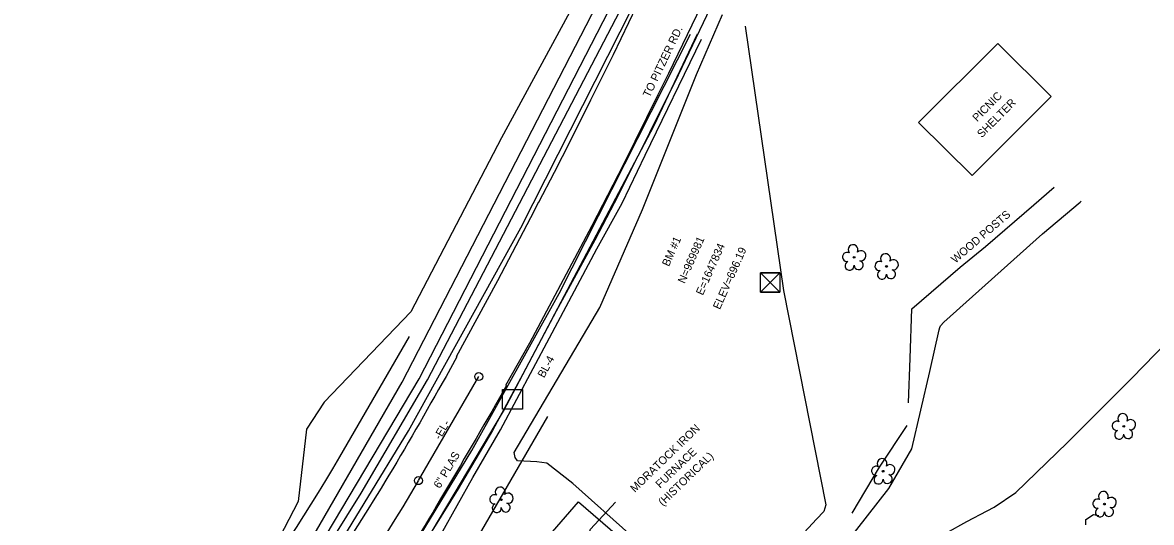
# Model space of a CAD drawing. Extents: x 1645945 to 2447332, y 713118 to 970361.
# Drawn here: x 1647554 to 1647977.1, y 969891.3 to 970078.7 of the extents above; entities that cross this region are included whole.
import ezdxf

# ---------------------------------------------------------------- set-up
doc = ezdxf.new("R2010")
doc.units = 0
for name, color, linetype in [('CTL Secondary Horizontal and Vertical CELL', 7, 'Continuous'), ('CTL Secondary Horizontal and Vertical Text', 7, 'Continuous'), ('CTL Vertical Benchmark CELL', 7, 'Continuous'), ('CTL Vertical Benchmark Text', 7, 'Continuous'), ('Exist Building', 7, 'Continuous'), ('Exist Building Text', 7, 'Continuous'), ('Exist Guardrail', 7, 'Continuous'), ('Exist Horizontal Alignment', 7, 'Continuous'), ('Exist Horizontal Alignment Direction Label', 7, 'Continuous'), ('Exist Horizontal Alignment Station Label', 7, 'Continuous'), ('Exist Hydro Jurisdictional Stream or Body of Water', 7, 'Continuous'), ('Exist Other Culture Fence Line', 7, 'Continuous'), ('Exist Other Culture Fence Line Leader', 7, 'Continuous'), ('Exist Other Culture Fence Line Text', 7, 'Continuous'), ('Exist Right of Way Line', 7, 'Continuous'), ('Exist Roads EOP', 7, 'Continuous'), ('Exist Roads EOP Text', 7, 'Continuous'), ('Exist Roads Soil', 7, 'Continuous'), ('Exist Utilities Sanitary Sewer Forced Main SUE LOS C', 7, 'Continuous'), ('Exist Utilities Sanitary Sewer Forced Main SUE LOS C Text', 7, 'Continuous'), ('Exist Utilities Telephone UG Cable SUE LOS C', 7, 'Continuous'), ('Exist Utilities Telephone UG Conduit SUE LOS B', 7, 'Continuous'), ('Exist Utilities Telephone UG FO SUE LOS C', 7, 'Continuous'), ('Exist Vegetation Tree CELL', 7, 'Continuous'), ('Exist Vegetation Woods Line', 7, 'Continuous')]:
    doc.layers.add(name, color=color, linetype=linetype)

msp = doc.modelspace()

# ---------------------------------------------------------------- linework, layer by layer
at = {"layer": 'CTL Secondary Horizontal and Vertical CELL'}
msp.add_line((1647737.61, 969937.44), (1647737.61, 969937.44), dxfattribs=at)
msp.add_lwpolyline([(1647733.94, 969941.14), (1647741.35, 969941.14), (1647741.35, 969933.71), (1647733.94, 969933.71)], close=True, dxfattribs=at)
at = {"layer": 'CTL Vertical Benchmark CELL'}
msp.add_line((1647834.21, 969981.25), (1647834.21, 969981.25), dxfattribs=at)
msp.add_line((1647834.21, 969981.25), (1647834.21, 969981.25), dxfattribs=at)
msp.add_lwpolyline([(1647830.61, 969984.84), (1647837.8, 969984.84), (1647837.8, 969977.65), (1647830.61, 969977.65)], close=True, dxfattribs=at)
msp.add_lwpolyline([(1647830.61, 969984.84), (1647837.8, 969984.84), (1647837.8, 969977.65), (1647830.61, 969977.65)], close=True, dxfattribs=at)
for points in [[(1647837.8, 969984.84), (1647830.61, 969977.65), (1647834.21, 969981.25), (1647837.8, 969977.65), (1647830.61, 969984.84)], [(1647834.21, 969981.25), (1647837.8, 969984.84), (1647830.61, 969984.84), (1647834.21, 969981.25)], [(1647837.8, 969984.84), (1647830.61, 969977.65), (1647834.21, 969981.25), (1647837.8, 969977.65), (1647830.61, 969984.84)], [(1647834.21, 969981.25), (1647837.8, 969984.84), (1647830.61, 969984.84), (1647834.21, 969981.25)], [(1647834.21, 969981.25), (1647830.61, 969977.65), (1647837.8, 969977.65), (1647834.21, 969981.25)], [(1647834.21, 969981.25), (1647830.61, 969977.65), (1647837.8, 969977.65), (1647834.21, 969981.25)]]:
    msp.add_lwpolyline(points, dxfattribs=at)
at = {"layer": 'Exist Building'}
msp.add_lwpolyline([(1647889.82, 970041.18), (1647909.9, 970021.39), (1647939.56, 970050.99), (1647919.51, 970070.87)], close=True, dxfattribs=at)
at = {"layer": 'Exist Guardrail'}
for points in [[(1647811.77, 970084.13), (1647799.78, 970058.98), (1647789, 970037.41), (1647777.22, 970013.91), (1647768.44, 969997.09), (1647760.77, 969982.88)], [(1647760.77, 969982.88), (1647754.03, 969970.46), (1647741.47, 969946.85), (1647730.08, 969925.76), (1647717.26, 969903.89), (1647707.96, 969889.08), (1647696.73, 969871.06), (1647684.96, 969853.08), (1647670.81, 969832.67), (1647653.24, 969808.63), (1647638.37, 969789.54), (1647629.29, 969778.66)]]:
    msp.add_lwpolyline(points, dxfattribs=at)
at = {"layer": 'Exist Horizontal Alignment'}
msp.add_line((1647702.37, 969906.97), (1647724.96, 969945.99), dxfattribs=at)
msp.add_arc((1647126.83, 970240.1), 665, 298.87121, 329.93673, dxfattribs=at)
at = {"layer": 'Exist Horizontal Alignment Station Label'}
for centre in [(1647724.96, 969945.99), (1647702.37, 969906.97)]:
    msp.add_circle(centre, 1.5, dxfattribs=at)
at = {"layer": 'Exist Hydro Jurisdictional Stream or Body of Water'}
msp.add_lwpolyline([(1647952.53, 969890.44), (1647952.46, 969892.39), (1647955.36, 969894.22), (1647957.42, 969893.91)], dxfattribs=at)
at = {"layer": 'Exist Other Culture Fence Line'}
for points in [[(1647887.25, 969971.32), (1647905.4, 969986.95), (1647914.92, 969994.73), (1647933.07, 970010.39), (1647940.6, 970017)], [(1647886.05, 969936.09), (1647886.68, 969952.9), (1647887.25, 969971.32)], [(1647864.88, 969894.79), (1647875.23, 969912.03), (1647885.58, 969927.64)]]:
    msp.add_lwpolyline(points, dxfattribs=at)
msp.add_lwpolyline([(1647788.87, 969876.21), (1647762.15, 969845.28), (1647735.67, 969868.17), (1647762.41, 969899.05)], close=True, dxfattribs=at)
at = {"layer": 'Exist Other Culture Fence Line Leader'}
msp.add_lwpolyline([(1647761.01, 969872.67), (1647766.89, 969888.75), (1647776.2, 969898.94)], dxfattribs=at)
at = {"layer": 'Exist Right of Way Line'}
for p, q in [((1647672.88, 969915.9), (1647698.99, 969961.02)), ((1647724.81, 969885.85), (1647750.92, 969930.96))]:
    msp.add_line(p, q, dxfattribs=at)
msp.add_arc((1647136.28, 970226.5), 620, 299.46236, 329.93673, dxfattribs=at)
at = {"layer": 'Exist Roads EOP'}
for p, q in [((1647716.78, 969953.44), (1647712.71, 969946.05)), ((1647735.42, 969942.61), (1647731.3, 969935.45))]:
    msp.add_line(p, q, dxfattribs=at)
for points in [[(1647747.48, 970011.4), (1647753.32, 970022.66), (1647759.35, 970034.39), (1647767.01, 970049.78), (1647775.46, 970066.77), (1647784.09, 970084.66), (1647789.56, 970095.71)], [(1647758.89, 969986.43), (1647767.54, 970002.65), (1647779.38, 970025.55), (1647792.2, 970051.77), (1647796.26, 970059.68), (1647806.67, 970081.44), (1647808.71, 970085.73)], [(1647716.61, 969953.53), (1647732.1, 969981.97), (1647744.49, 970005.6), (1647747.5, 970011.45)], [(1647735.19, 969942.75), (1647744.08, 969958.63), (1647758.89, 969986.43)]]:
    msp.add_lwpolyline(points, dxfattribs=at)
for points in [[(1647712.71, 969946.05), (1647689.83, 969906.56), (1647665.85, 969869.13), (1647637.34, 969829.12), (1647607.92, 969794.57), (1647574.53, 969760.72), (1647538.69, 969730.5), (1647499.85, 969702.79), (1647457.34, 969676.33), (1647411.66, 969651.37), (1647366.8, 969630.41), (1647321.37, 969611.83), (1647279.28, 969597.97), (1647224.82, 969583.15), (1647179.92, 969574.15), (1647132.17, 969565.53), (1647083.22, 969557.97), (1647036.22, 969550.58), (1646989.26, 969543.73)], [(1647731.3, 969935.45), (1647707.71, 969895.07), (1647684.27, 969857.13), (1647654.38, 969814.5), (1647624.46, 969779.25), (1647589.97, 969744.66), (1647553.5, 969714.01), (1647512.43, 969684.95), (1647469.3, 969658.19), (1647421.26, 969632.07), (1647375.68, 969609.9), (1647329.15, 969590.49), (1647286.02, 969576.26), (1647230.19, 969561.18), (1647183.04, 969552.75), (1647135.89, 969544.58), (1647086.4, 969536.99), (1647040.14, 969529.53), (1646992.05, 969522.32)]]:
    msp.add_spline(points, degree=3, dxfattribs=at)
at = {"layer": 'Exist Roads Soil'}
for points in [[(1647825.16, 969840.29), (1647854.68, 969873.27), (1647878.69, 969904.08), (1647887.29, 969918.9), (1647894, 969947.84), (1647897.55, 969963.48), (1647897.73, 969964.36), (1647898, 969965.01), (1647899.35, 969966.38), (1647936.25, 969999.54), (1647950.33, 970011.39), (1647950.78, 970011.69)], [(1647833.9, 969820.27), (1647843.63, 969831.63), (1647859.7, 969851.23), (1647864.42, 969856.65), (1647872.24, 969865.05), (1647876.68, 969870.11), (1647881, 969874.71), (1647884.73, 969878.03), (1647892.67, 969883.14), (1647907.86, 969891.64), (1647915.49, 969895.7), (1647918.11, 969897.01), (1647926.28, 969902.5), (1647945.52, 969921.1), (1647969.9, 969945.49), (1647987.24, 969963.4), (1648002.75, 969980.2), (1648005.41, 969983.22)]]:
    msp.add_lwpolyline(points, dxfattribs=at)
at = {"layer": 'Exist Utilities Sanitary Sewer Forced Main SUE LOS C'}
msp.add_lwpolyline([(1647621.71, 969772.62), (1647654.05, 969809.43), (1647680.79, 969846.9), (1647702.42, 969879.41), (1647734.22, 969933.03), (1647790.69, 970040.12), (1647806.93, 970074.53)], dxfattribs=at)
at = {"layer": 'Exist Utilities Telephone UG Cable SUE LOS C'}
for points in [[(1647301.18, 969607.49), (1647346.35, 969625.33), (1647402.72, 969651.12), (1647431.08, 969666.24), (1647439.41, 969670.62), (1647442.16, 969672.78), (1647445.5, 969676.48), (1647448.63, 969678.56), (1647474.06, 969693.41), (1647520.52, 969726.92), (1647556, 969754.87), (1647590.11, 969785.42), (1647617.35, 969813.54), (1647647.46, 969852.3), (1647702.67, 969945.18), (1647775.84, 970087.47)], [(1647299.74, 969604.87), (1647344.43, 969621.93), (1647402.05, 969647.91), (1647428.7, 969661.61), (1647441.47, 969668.79), (1647444.57, 969671.27), (1647446.47, 969673.44), (1647447.93, 969674.84), (1647451.1, 969676.98), (1647475.41, 969691.19), (1647501.84, 969708.82), (1647529.96, 969729.71), (1647548.6, 969744.41), (1647576.21, 969768.81), (1647599.16, 969791.2), (1647624.94, 969819.94), (1647649.96, 969852.56), (1647680.88, 969902.23), (1647705.82, 969944.72), (1647779.36, 970085.84)], [(1647294.11, 969544.68), (1647330.92, 969585.92), (1647342.26, 969590.26), (1647406.15, 969619.43), (1647450.3, 969642.78), (1647488.96, 969665.16), (1647521.25, 969685.99), (1647545.76, 969703.5), (1647563.98, 969716.93), (1647573.87, 969725.16), (1647593.32, 969742.95), (1647627.6, 969780.32), (1647655.82, 969815.07), (1647672.99, 969839.14), (1647691.44, 969867.28), (1647722.34, 969918.27), (1647755.1, 969977.16), (1647804.4, 970074.3)]]:
    msp.add_lwpolyline(points, dxfattribs=at)
at = {"layer": 'Exist Utilities Telephone UG Conduit SUE LOS B'}
msp.add_lwpolyline([(1647528.7, 969688.64), (1647565.5, 969715.45), (1647584.81, 969732.68), (1647602.51, 969750.52), (1647610.22, 969758.56), (1647624.57, 969770.24), (1647632, 969778.64), (1647655.51, 969806.51), (1647671.15, 969829.51), (1647684.31, 969848.46), (1647700.06, 969870.14), (1647710.99, 969887.15), (1647722.81, 969908.11), (1647733.12, 969926.03), (1647751.45, 969960.54), (1647769.23, 969993.85), (1647778.74, 970010.99), (1647787.31, 970029.01), (1647808.48, 970072.42)], dxfattribs=at)
at = {"layer": 'Exist Utilities Telephone UG FO SUE LOS C'}
for points in [[(1647289.7, 969609.34), (1647343.59, 969629.58), (1647397.62, 969653.63), (1647450.96, 969681.88), (1647471.14, 969694.21), (1647529.28, 969736.65), (1647578.89, 969778.78), (1647616.07, 969816.36), (1647645.02, 969855.2), (1647696.33, 969943.83), (1647771.33, 970089.55)], [(1647291.19, 969605.96), (1647345.09, 969627.35), (1647401.66, 969653.17), (1647434.03, 969670.53), (1647438.26, 969672.06), (1647445.18, 969672.38), (1647450.09, 969673.09), (1647455.34, 969675.46), (1647473.43, 969686.09), (1647508.86, 969709.29), (1647532.76, 969727.04), (1647549.35, 969740.28), (1647575.78, 969764.21), (1647609.03, 969797.83), (1647638.13, 969832.64), (1647665.39, 969871.17), (1647698.7, 969925.68), (1647740.76, 970001.75), (1647782.56, 970084.37)]]:
    msp.add_lwpolyline(points, dxfattribs=at)
at = {"layer": 'Exist Vegetation Tree CELL'}
for p, q in [((1647865.66, 969990.68), (1647865.66, 969990.68)), ((1647877.8, 969987.29), (1647877.8, 969987.29)), ((1647966.71, 969927.35), (1647966.71, 969927.35)), ((1647876.53, 969910.5), (1647876.53, 969910.5)), ((1647733.43, 969899.81), (1647733.43, 969899.81)), ((1647959.48, 969898.18), (1647959.48, 969898.18))]:
    msp.add_line(p, q, dxfattribs=at)
for centre in [(1647865.66, 969990.68), (1647877.8, 969987.29), (1647966.71, 969927.35), (1647876.53, 969910.5), (1647733.43, 969899.81), (1647959.48, 969898.18)]:
    msp.add_circle(centre, 0.326, dxfattribs=at)
for centre, radius, start, end in [((1647865.27, 969993.56), 1.86, 330.1651, 219.7134), ((1647863.05, 969990.84), 1.73, 62.6636, 279.3457), ((1647868.21, 969991.27), 1.9, 257.1011, 134.1999), ((1647877.42, 969990.16), 1.86, 330.1651, 219.7134), ((1647863.95, 969987.56), 1.69, 111.5671, 6.231), ((1647867.33, 969987.79), 1.7, 181.2822, 74.56), ((1647875.2, 969987.44), 1.73, 62.6636, 279.3457), ((1647876.1, 969984.17), 1.69, 111.5671, 6.231), ((1647879.47, 969984.39), 1.7, 181.2822, 74.56), ((1647880.35, 969987.88), 1.9, 257.1011, 134.1999), ((1647966.33, 969930.23), 1.86, 330.1651, 219.7134), ((1647964.1, 969927.51), 1.73, 62.6636, 279.3457), ((1647969.26, 969927.94), 1.9, 257.1011, 134.1999), ((1647965.01, 969924.23), 1.69, 111.5671, 6.231), ((1647968.38, 969924.45), 1.7, 181.2822, 74.56), ((1647876.14, 969913.37), 1.86, 330.1651, 219.7134), ((1647873.92, 969910.65), 1.73, 62.6636, 279.3457), ((1647879.08, 969911.09), 1.9, 257.1011, 134.1999), ((1647874.82, 969907.38), 1.69, 111.5671, 6.231), ((1647878.2, 969907.6), 1.7, 181.2822, 74.56), ((1647730.82, 969899.96), 1.73, 62.6636, 279.3457), ((1647733.04, 969902.68), 1.86, 330.1651, 219.7134), ((1647735.98, 969900.4), 1.9, 257.1011, 134.1999), ((1647959.1, 969901.05), 1.86, 330.1651, 219.7134), ((1647731.72, 969896.69), 1.69, 111.5671, 6.231), ((1647735.1, 969896.91), 1.7, 181.2822, 74.56), ((1647956.88, 969898.33), 1.73, 62.6636, 279.3457), ((1647961.15, 969895.28), 1.7, 181.2822, 74.56), ((1647962.03, 969898.77), 1.9, 257.1011, 134.1999), ((1647957.78, 969895.06), 1.69, 111.5671, 6.231)]:
    msp.add_arc(centre, radius, start, end, dxfattribs=at)
at = {"layer": 'Exist Vegetation Woods Line'}
for points in [[(1647769.66, 970106.07), (1647759.87, 970084.05), (1647733.57, 970035.54)], [(1647824.83, 970077.33), (1647839.22, 969978.28), (1647855.08, 969897.94), (1647854.31, 969895.44), (1647851.54, 969892.5), (1647824.08, 969862.82), (1647821.91, 969862.11), (1647808.81, 969860.85), (1647791.79, 969849.82), (1647790.19, 969849.9), (1647792.99, 969876.68), (1647792.7, 969877.05), (1647782.35, 969886.2), (1647760.24, 969905.93), (1647750.48, 969913.52), (1647750.47, 969913.55), (1647746.78, 969914.04), (1647739.49, 969914.41), (1647738.63, 969915.59), (1647738.2, 969917.48), (1647770.38, 969971.84), (1647786.35, 970008.59), (1647806.57, 970059.22), (1647816.29, 970081.77)], [(1647733.57, 970035.54), (1647699.58, 969970.2), (1647667.04, 969936.34), (1647660.42, 969926.24), (1647657.35, 969899.17), (1647638.11, 969862.07), (1647624.3, 969842.67), (1647617.2, 969826.74), (1647600.44, 969813.37), (1647575.42, 969798.45), (1647547.21, 969775.36)]]:
    msp.add_lwpolyline(points, dxfattribs=at)

# ---------------------------------------------------------------- texts
at = {"layer": 'CTL Secondary Horizontal and Vertical Text'}
msp.add_text('BL-4', height=3, rotation=61.728, dxfattribs=at).set_placement((1647749.46, 969945.27))
at = {"layer": 'CTL Vertical Benchmark Text'}
for s, p in [('BM #1', (1647796.25, 969987.03)), ('N=969981', (1647802.16, 969980.62)), ('E=1647834', (1647808.96, 969976.22)), ('ELEV=696.19', (1647815.35, 969970.9))]:
    msp.add_text(s, height=3, rotation=66.1258, dxfattribs=at).set_placement(p)
at = {"layer": 'Exist Building Text'}
for s, p in [('PICNIC', (1647911.76, 970041.32)), ('SHELTER', (1647913.53, 970035.3))]:
    msp.add_text(s, height=3, rotation=45.1587, dxfattribs=at).set_placement(p)
at = {"layer": 'Exist Horizontal Alignment Direction Label'}
msp.add_text('-EL-', height=3, rotation=59.9367, dxfattribs=at).set_placement((1647710.53, 969922.07))
at = {"layer": 'Exist Other Culture Fence Line Text'}
for s, rotation, p in [('WOOD POSTS', 40.7743, (1647903.62, 969988.28)), ('MORATOCK IRON', 44.091, (1647783.48, 969902.39)), ('FURNACE', 44.091, (1647792.97, 969903.92)), ('(HISTORICAL)', 44.091, (1647794, 969897.26))]:
    msp.add_text(s, height=3, rotation=rotation, dxfattribs=at).set_placement(p)
at = {"layer": 'Exist Roads EOP Text'}
msp.add_text('TO PITZER RD.', height=3, rotation=64.4337, dxfattribs=at).set_placement((1647789.03, 970050.37))
at = {"layer": 'Exist Utilities Sanitary Sewer Forced Main SUE LOS C Text'}
msp.add_text('6" PLAS', height=3, rotation=59.3282, dxfattribs=at).set_placement((1647710.4, 969903.8))

doc.saveas('drawing.dxf')
